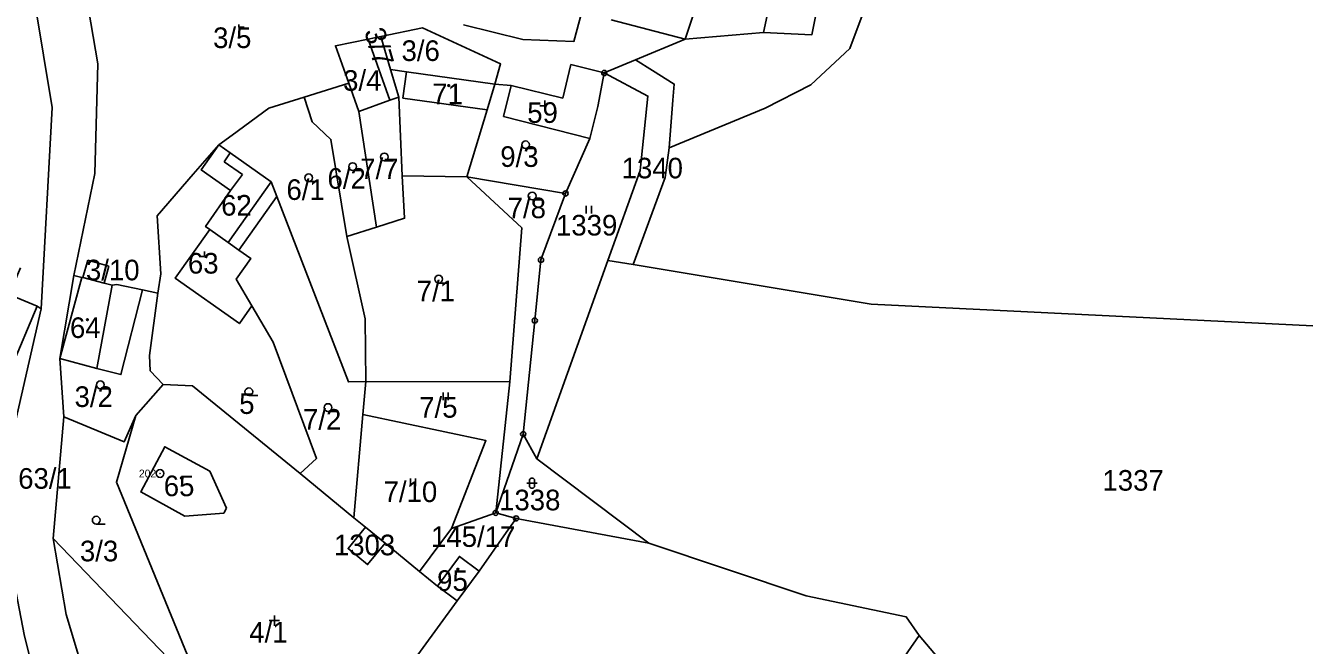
# Model space of a CAD drawing. Extents: x -564516 to -563466, y -1163913 to -1163170.
# Drawn here: x -564146.8 to -563898.7, y -1163610.3 to -1163490 of the extents above; entities that cross this region are included whole.
import ezdxf

# ---------------------------------------------------------------- set-up
doc = ezdxf.new("R2010")
doc.units = 0
for name, color, linetype in [('Hranice parcel', 7, 'Continuous'), ('Parcelní čísla', 7, 'Continuous'), ('Vnitřní kresba', 7, 'Continuous'), ('Značky bodu BP', 7, 'Continuous'), ('Značky budov', 7, 'Continuous'), ('Značky kultur', 7, 'Continuous')]:
    doc.layers.add(name, color=color, linetype=linetype)

msp = doc.modelspace()

# ---------------------------------------------------------------- linework, layer by layer
at = {"layer": 'Hranice parcel'}
for p, q in [((-564003.59, -1163491.36), (-564001.49, -1163481.27)), ((-564018.83, -1163492.67), (-564033.19, -1163488.88)), ((-564080.36, -1163492.63), (-564077.86, -1163492.12)), ((-564076.1, -1163504.52), (-564080.36, -1163492.63)), ((-564077.86, -1163492.12), (-564075.98, -1163498.54)), ((-564018.83, -1163492.67), (-564028.46, -1163496.69)), ((-564003.59, -1163491.36), (-564018.83, -1163492.67)), ((-564028.46, -1163496.69), (-564034.52, -1163499.22)), ((-564075.98, -1163498.54), (-564074.41, -1163503.9)), ((-564084.1, -1163501.17), (-564092.76, -1163503.91)), ((-564082.12, -1163506.7), (-564084.1, -1163501.17)), ((-564052.59, -1163501.62), (-564055.78, -1163501.39)), ((-564021.23, -1163504.52), (-564020.95, -1163501.38)), ((-564076.1, -1163504.52), (-564082.12, -1163506.7)), ((-564074.41, -1163503.9), (-564076.1, -1163504.52)), ((-564074.41, -1163503.9), (-564073.71, -1163519.16)), ((-564021.9, -1163513.74), (-564021.23, -1163504.52)), ((-564078.72, -1163529.15), (-564082.12, -1163506.7)), ((-564021.9, -1163513.74), (-564003.29, -1163506.07)), ((-564042.03, -1163522.61), (-564037.34, -1163511.95)), ((-564109.29, -1163513.17), (-564114.3, -1163518.86)), ((-564022.73, -1163519.5), (-564021.9, -1163513.74)), ((-564073.71, -1163519.16), (-564061.18, -1163519.39)), ((-564042.03, -1163522.61), (-564061.18, -1163519.39)), ((-564028.91, -1163536.42), (-564022.73, -1163519.5)), ((-564105.44, -1163533.59), (-564098.08, -1163523.21)), ((-564084.46, -1163530.94), (-564078.72, -1163529.15)), ((-564135.68, -1163538.95), (-564134.76, -1163535.58)), ((-564134.76, -1163535.58), (-564130.65, -1163536.7)), ((-564130.65, -1163536.7), (-564131.56, -1163540.01)), ((-564033.84, -1163535.6), (-564047.59, -1163574.1)), ((-564033.84, -1163535.6), (-564028.91, -1163536.42)), ((-564137.43, -1163538.5), (-564140.18, -1163554.63)), ((-564131.56, -1163540.01), (-564135.68, -1163538.95)), ((-564130.03, -1163540.41), (-564131.56, -1163540.01)), ((-564129.13, -1163540.27), (-564130.03, -1163540.41)), ((-564124.15, -1163541.32), (-564129.13, -1163540.27)), ((-564121.18, -1163541.94), (-564124.15, -1163541.32)), ((-564149.67, -1163556.63), (-564144.59, -1163544.5)), ((-564143.77, -1163544.97), (-564144.59, -1163544.5)), ((-564140.18, -1163554.63), (-564139.41, -1163565.96)), ((-564120.1, -1163559.69), (-564122.64, -1163557.02)), ((-564125.43, -1163565.71), (-564120.1, -1163559.69)), ((-564081.35, -1163565.54), (-564080.79, -1163559.09)), ((-564080.79, -1163559.09), (-564052.86, -1163559.2)), ((-564055.59, -1163584.6), (-564052.86, -1163559.2)), ((-564139.41, -1163565.96), (-564141.45, -1163589.58)), ((-564083.1, -1163585.56), (-564081.35, -1163565.54)), ((-564055.59, -1163584.6), (-564050.25, -1163569.33)), ((-564050.25, -1163569.33), (-564047.59, -1163574.1)), ((-564047.59, -1163574.1), (-564025.86, -1163590.51)), ((-564093.56, -1163576.99), (-564083.1, -1163585.56)), ((-564064.14, -1163587.67), (-564055.59, -1163584.6)), ((-564051.64, -1163585.68), (-564055.59, -1163584.6)), ((-564080.86, -1163587.4), (-564083.1, -1163585.56)), ((-564025.86, -1163590.51), (-564051.64, -1163585.68)), ((-564141.45, -1163589.58), (-564112.22, -1163619.96)), ((-564077.06, -1163590.51), (-564080.86, -1163587.4)), ((-564064.14, -1163587.67), (-564070.36, -1163596)), ((-564070.36, -1163596), (-564077.06, -1163590.51)), ((-564070.36, -1163596), (-564066.89, -1163598.84)), ((-564063.05, -1163601.67), (-564058.79, -1163595.9)), ((-564066.89, -1163598.84), (-564063.05, -1163601.67)), ((-564092.3, -1163641.63), (-564063.05, -1163601.67)), ((-563945.88, -1163641.11), (-563973.39, -1163608.38))]:
    msp.add_line(p, q, dxfattribs=at)
for points in [[(-564143.77, -1163544.97), (-564141.64, -1163505.89), (-564145.04, -1163485.62), (-564150.7, -1163460.95), (-564167.69, -1163413.52), (-564175.8, -1163398.73), (-564196.49, -1163371.97), (-564199.67, -1163364.72)], [(-563978.16, -1163460.35), (-563977.81, -1163470.18), (-563986.9, -1163494.46), (-563994.41, -1163501.54), (-564003.29, -1163506.07), (-564021.9, -1163513.74)], [(-563986.9, -1163494.46), (-563977.81, -1163470.18), (-563978.16, -1163460.35)], [(-563988.32, -1163461.72), (-563994.27, -1163491.83), (-564003.59, -1163491.36)], [(-564032.65, -1163483.65), (-564032.18, -1163483.66), (-564032.1, -1163484.76), (-564017.32, -1163488.18), (-564018.83, -1163492.67)], [(-564134.63, -1163486.82), (-564132.78, -1163497.42), (-564133.38, -1163518.72), (-564137.43, -1163538.5)], [(-564061.85, -1163489.87), (-564050.33, -1163492.71), (-564040.4, -1163493.1), (-564038.9, -1163487.37)], [(-564080.36, -1163492.63), (-564086.69, -1163493.92), (-564084.1, -1163501.17)], [(-564077.86, -1163492.12), (-564069.81, -1163490.48), (-564054.63, -1163497.47), (-564055.78, -1163501.39)], [(-564028.91, -1163536.42), (-563982.72, -1163544.1), (-563870.61, -1163549.59), (-563828.67, -1163493.21)], [(-564003.29, -1163506.07), (-563994.41, -1163501.54), (-563986.9, -1163494.46)], [(-564034.52, -1163499.22), (-564040.98, -1163497.58), (-564042.58, -1163504.09), (-564052.59, -1163501.62)], [(-564028.46, -1163496.69), (-564025.15, -1163498.74), (-564020.95, -1163501.38), (-564021.23, -1163504.52), (-564021.9, -1163513.74)], [(-564020.95, -1163501.38), (-564025.15, -1163498.74), (-564028.46, -1163496.69)], [(-564055.78, -1163501.39), (-564072.88, -1163498.98), (-564075.98, -1163498.54)], [(-564037.34, -1163511.95), (-564035.8, -1163505.76), (-564034.52, -1163499.22)], [(-564034.52, -1163499.22), (-564026.04, -1163503.72), (-564027.54, -1163518.14), (-564033.84, -1163535.6)], [(-564061.18, -1163519.39), (-564057.24, -1163506.38), (-564055.78, -1163501.39)], [(-564052.59, -1163501.62), (-564054.07, -1163507.64), (-564037.34, -1163511.95)], [(-564092.76, -1163503.91), (-564099.6, -1163506.08), (-564106.7, -1163511.31), (-564109.29, -1163513.17)], [(-564084.46, -1163530.94), (-564087.57, -1163512.11), (-564091.17, -1163508.73), (-564092.76, -1163503.91)], [(-564109.29, -1163513.17), (-564112.74, -1163518.03), (-564107.04, -1163522.06), (-564111.89, -1163529.04), (-564111.07, -1163529.61)], [(-564098.08, -1163523.21), (-564099.13, -1163520.36), (-564107.09, -1163514.73), (-564109.29, -1163513.17)], [(-564021.9, -1163513.74), (-564022.73, -1163519.5), (-564028.91, -1163536.42)], [(-564114.3, -1163518.86), (-564121.28, -1163526.92), (-564120.58, -1163538.19), (-564121.18, -1163541.94)], [(-564073.71, -1163519.16), (-564073.26, -1163527.42), (-564078.72, -1163529.15)], [(-564052.86, -1163559.2), (-564050.52, -1163529.28), (-564061.18, -1163519.39)], [(-564050.25, -1163569.33), (-564048, -1163547.27), (-564046.8, -1163535.5), (-564042.03, -1163522.61)], [(-564098.08, -1163523.21), (-564084.18, -1163559.19), (-564080.79, -1163559.09)], [(-564111.07, -1163529.61), (-564117.77, -1163539.08), (-564105.32, -1163547.88), (-564102.89, -1163544.44)], [(-564111.07, -1163529.61), (-564107.48, -1163532.15), (-564105.44, -1163533.59)], [(-564080.79, -1163559.09), (-564080.89, -1163546.94), (-564084.46, -1163530.94)], [(-564102.89, -1163544.44), (-564105.94, -1163539.23), (-564103.12, -1163535.23), (-564105.44, -1163533.59)], [(-564144.59, -1163544.5), (-564150.02, -1163542.22), (-564147.82, -1163537.06)], [(-564135.68, -1163538.95), (-564135.89, -1163538.9), (-564137.43, -1163538.5)], [(-564140.18, -1163554.63), (-564133.01, -1163556.6), (-564128.31, -1163557.75), (-564124.15, -1163541.32)], [(-564122.64, -1163557.02), (-564122.78, -1163554.08), (-564121.18, -1163541.94)], [(-564141.75, -1163629.73), (-564147.11, -1163608.19), (-564150.44, -1163590.7), (-564149.91, -1163571.99), (-564143.77, -1163544.97)], [(-564093.56, -1163576.99), (-564090.33, -1163574.05), (-564098.76, -1163551.48), (-564102.89, -1163544.44)], [(-564120.1, -1163559.69), (-564114.4, -1163559.92), (-564093.56, -1163576.99)], [(-564139.41, -1163565.96), (-564127.69, -1163570.84), (-564125.43, -1163565.71)], [(-564112.22, -1163619.96), (-564129.19, -1163578.66), (-564125.43, -1163565.71)], [(-564081.35, -1163565.54), (-564057.47, -1163570.58), (-564064.14, -1163587.67)], [(-564107.84, -1163583.68), (-564111.09, -1163576.51), (-564119.82, -1163571.78), (-564124.45, -1163580.53), (-564115.93, -1163585.25), (-564108.37, -1163584.67), (-564107.84, -1163583.68)], [(-564058.79, -1163595.9), (-564053.56, -1163588.43), (-564051.64, -1163585.68)], [(-564141.45, -1163589.58), (-564138.93, -1163604.36), (-564128.21, -1163640.02)], [(-564080.86, -1163587.4), (-564084.24, -1163591.54), (-564080.45, -1163594.65), (-564077.06, -1163590.51)], [(-563973.39, -1163608.38), (-563975.93, -1163604.8), (-563995.32, -1163600.73), (-564025.86, -1163590.51)], [(-564058.79, -1163595.9), (-564062.63, -1163593.07), (-564066.89, -1163598.84)], [(-564038.32, -1163697.37), (-564037.15, -1163696.07), (-563993.61, -1163632.54), (-563977.25, -1163613.92), (-563973.39, -1163608.38)]]:
    msp.add_lwpolyline(points, dxfattribs=at)
at = {"layer": 'Vnitřní kresba'}
for p, q in [((-564072.88, -1163498.98), (-564073.58, -1163504.08)), ((-564073.58, -1163504.08), (-564057.24, -1163506.38)), ((-564108.3, -1163516.44), (-564107.09, -1163514.73)), ((-564104.75, -1163518.95), (-564108.3, -1163516.44)), ((-564107.04, -1163522.06), (-564104.75, -1163518.95)), ((-564099.13, -1163520.36), (-564107.48, -1163532.15)), ((-564135.89, -1163538.9), (-564140.18, -1163554.63)), ((-564130.03, -1163540.41), (-564133.01, -1163556.6))]:
    msp.add_line(p, q, dxfattribs=at)
at = {"layer": 'Značky bodu BP'}
for centre, radius in [((-564034.52, -1163499.22), 0.5), ((-564034.52, -1163499.22), 0.0303), ((-564042.03, -1163522.61), 0.5), ((-564042.03, -1163522.61), 0.0303), ((-564046.8, -1163535.5), 0.5), ((-564046.8, -1163535.5), 0.0303), ((-564048, -1163547.27), 0.5), ((-564048, -1163547.27), 0.0303), ((-564050.25, -1163569.33), 0.5), ((-564050.25, -1163569.33), 0.0303), ((-564120.72, -1163576.96), 0.75), ((-564120.72, -1163576.96), 0.03), ((-564055.59, -1163584.6), 0.5), ((-564055.59, -1163584.6), 0.0303), ((-564051.64, -1163585.68), 0.5), ((-564051.64, -1163585.68), 0.0303)]:
    msp.add_circle(centre, radius, dxfattribs=at)
at = {"layer": 'Značky budov'}
for centre in [(-564064.7, -1163501.67), (-564105.39, -1163523.36), (-564134.82, -1163547.11), (-564116.56, -1163577.82), (-564062.93, -1163595.56)]:
    msp.add_circle(centre, 0.175, dxfattribs=at)
at = {"layer": 'Značky kultur'}
for p, q in [((-564105.41, -1163489.84), (-564105.41, -1163490.34)), ((-564105.41, -1163490.34), (-564104.41, -1163490.34)), ((-564046.05, -1163505.57), (-564046.05, -1163504.57)), ((-564047.05, -1163505.57), (-564046.05, -1163505.57)), ((-564049.79, -1163513.9), (-564048.04, -1163513.9)), ((-564077.2, -1163516.28), (-564075.45, -1163516.28)), ((-564083.34, -1163518.14), (-564081.59, -1163518.14)), ((-564091.87, -1163520.31), (-564090.12, -1163520.31)), ((-564048.51, -1163523.86), (-564046.76, -1163523.86)), ((-564038.01, -1163526.5), (-564038.01, -1163525)), ((-564037.01, -1163526.5), (-564037.01, -1163525)), ((-564113.1, -1163534.86), (-564112.1, -1163534.86)), ((-564112.1, -1163534.86), (-564112.1, -1163533.86)), ((-564066.65, -1163539.99), (-564064.9, -1163539.99)), ((-564132.3, -1163560.5), (-564130.55, -1163560.5)), ((-564103.49, -1163561.85), (-564101.74, -1163561.85)), ((-564065.8, -1163562.75), (-564065.8, -1163561.25)), ((-564064.8, -1163562.75), (-564064.8, -1163561.25)), ((-564088.14, -1163564.91), (-564086.39, -1163564.91)), ((-564072.15, -1163579.42), (-564072.15, -1163577.92)), ((-564071.15, -1163579.42), (-564071.15, -1163577.92)), ((-564049.54, -1163578.84), (-564047.54, -1163578.84)), ((-564049.04, -1163578.34), (-564049.04, -1163579.34)), ((-564048.04, -1163579.34), (-564048.04, -1163578.34)), ((-564133.11, -1163586.77), (-564131.36, -1163586.77)), ((-564098.53, -1163606.52), (-564098.53, -1163604.52)), ((-564097.53, -1163605.52), (-564099.53, -1163605.52))]:
    msp.add_line(p, q, dxfattribs=at)
for centre in [(-564049.79, -1163513.15), (-564077.2, -1163515.53), (-564083.34, -1163517.39), (-564091.87, -1163519.56), (-564048.51, -1163523.11), (-564066.65, -1163539.24), (-564132.3, -1163559.75), (-564103.49, -1163561.1), (-564088.14, -1163564.16), (-564133.11, -1163586.02)]:
    msp.add_circle(centre, 0.75, dxfattribs=at)
for centre, start, end in [((-564048.54, -1163578.34), 0, 180), ((-564048.54, -1163579.34), 180, 359.9879)]:
    msp.add_arc(centre, 0.5, start, end, dxfattribs=at)

# ---------------------------------------------------------------- texts
at = {"layer": 'Parcelní čísla'}
for s, p in [('3/5', (-564110.43, -1163494.38)), ('3/6', (-564073.86, -1163496.89)), ('3/4', (-564085.2, -1163502.68)), ('71', (-564067.91, -1163505.28)), ('59', (-564049.47, -1163508.91)), ('9/3', (-564054.7, -1163517.45)), ('6/2', (-564088.23, -1163521.69)), ('7/7', (-564081.88, -1163519.83)), ('1340', (-564031.15, -1163519.68)), ('6/1', (-564096.19, -1163523.86)), ('62', (-564108.87, -1163526.91)), ('7/8', (-564053.27, -1163527.41)), ('1339', (-564043.89, -1163530.77)), ('63', (-564115.31, -1163538.16)), ('3/10', (-564135.1, -1163539.47)), ('7/1', (-564070.91, -1163543.54)), ('64', (-564138.2, -1163550.66)), ('3/2', (-564137.31, -1163564.05)), ('5', (-564105.37, -1163565.4)), ('7/5', (-564070.43, -1163566.13)), ('7/2', (-564092.98, -1163568.46)), ('1163/1', (-564154.2, -1163579.92)), ('1337', (-563937.85, -1163580.3)), ('65', (-564120, -1163581.37)), ('7/10', (-564077.34, -1163582.51)), ('1338', (-564054.93, -1163584.11)), ('145/17', (-564068.13, -1163591.21)), ('1303', (-564086.99, -1163592.84)), ('3/3', (-564136.27, -1163594.01)), ('95', (-564066.95, -1163599.75)), ('4/1', (-564103.41, -1163609.77))]:
    msp.add_text(s, height=4, dxfattribs=at).set_placement(p)
msp.add_text('3/7', height=4, rotation=286, dxfattribs=at).set_placement((-564081.14, -1163491.1))
at = {"layer": 'Značky bodu BP'}
msp.add_text('202', height=1.5, dxfattribs=at).set_placement((-564124.82, -1163577.71))

doc.saveas('drawing.dxf')
